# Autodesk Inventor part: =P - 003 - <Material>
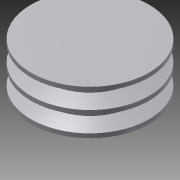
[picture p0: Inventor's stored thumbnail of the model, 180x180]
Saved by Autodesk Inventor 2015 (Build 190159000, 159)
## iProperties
Created: 2007-02
Part Number: =P - 003 - <Material>
Material: Aluminum-6061
Document SubType Name: Modeling
Designer: Autodesk, Inc.
Density: 2.71 g/cm^3
Mass: 491.294 g
Surface Area: 311.57 cm^2
Volume: 181.289 cm^3
Description: =Pulley - <Mass>
Appearance: Aluminum - Flat
CustomPartVersion: 1
Author: Autodesk, Inc.
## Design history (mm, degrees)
sketch "Main Sketch"
  geometry: L1 (0, 34.925)-(46.355, 34.925); L2 (46.355, 34.925)-(46.355, 15.804); L3 (46.355, 15.804)-(34.671, 12.232); L4 (34.671, 12.232)-(34.671, 6.818); L5 (34.671, 6.818)-(46.355, 3.246); L6 (46.355, 3.246)-(46.355, 0); L7 (46.355, 0)-(0, 0); L8 (43.18, 14.834)-(43.18, 4.216); L9 (0, 34.925)-(0, 0); L10 (34.671, 9.525)-(43.18, 9.525); L11 (46.355, 15.804)-(46.355, 3.246); L12 (0, -6.985)-(0, 41.91) reference
  constraints: 22 end point, 5 perpendicular, 3 collinear, 2 midpoint, 2 point on line, 1 parallel
  dimensions: "d0" = 10.6172 distance of L8.start L8.end (= da_Bw); "d1" = 34 deg angle of L3 L5 (= da_Alfa); "d2" = 3.175 distance between parallel lines of L2 L8 (= da_c); "d6" = 34.925 distance between parallel lines of L7 L1 (computed from d5, da_ng, da_Sg); "d21" = 86.36 diameter of L8 L12 (= da_Dw); "d25" = 11.684 distance between parallel lines of L4 L11 (= da_Hd); "d27" = 9.525 distance between parallel lines of L7 L10 (= da_Se)
node "Belt Plane"
revolve "Body" stored, may be unused: angle "d7" = 90 deg
revolve "Groove" stored, may be unused: angle "d15" = 90 deg
fillet "Fillet External" dims "d8" = 0 (computed from da_r1), "d10" = 0, "da_r1" = 0 [user parameter; used in 1 equation term]
fillet "Fillet Internal" dims "d9" = 0 (computed from da_r2), "d11" = 0, "da_r2" = 0 [user parameter; used in 1 equation term]
pattern_linear "Groove Pattern" dims "d18" = 15.875 (= da_Sg)
body "Solid1"
other parameters: "d5" = 9.525 (= da_Se), "da_Bw" = 10.6172 [user parameter; used in 1 equation term], "da_Alfa" = 34 deg [user parameter; used in 1 equation term], "da_c" = 3.175 [user parameter; used in 1 equation term], "da_Dw" = 86.36 [user parameter; used in 1 equation term], "da_Hd" = 11.684 [user parameter; used in 1 equation term], "da_Se" = 9.525 [user parameter; used in 2 equation terms], "da_Sg" = 15.875 [user parameter; used in 2 equation terms], "d24" = 0, "d26" = 0
